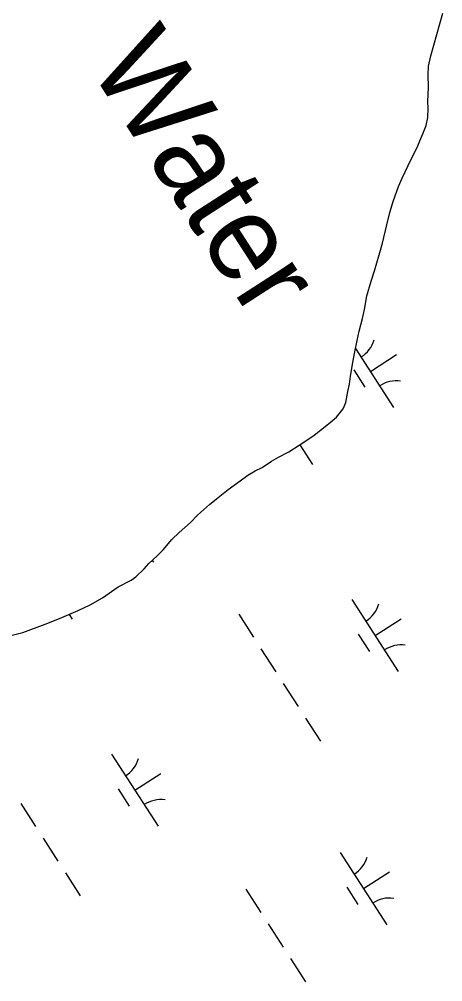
# Model space of a CAD drawing. Extents: x 3937982 to 3958556, y 219448 to 241894.
# Drawn here: x 3948264 to 3948510, y 226065 to 226625 of the extents above; entities that cross this region are included whole.
import ezdxf

# ---------------------------------------------------------------- set-up
doc = ezdxf.new("R2010")
doc.units = 0
for name, color, linetype in [('V-RIVR-IDEN', 7, 'Continuous'), ('V-TOPO-SHOR', 7, 'Continuous'), ('V-WETL-SWMP', 7, 'Continuous')]:
    doc.layers.add(name, color=color, linetype=linetype)

msp = doc.modelspace()

# ---------------------------------------------------------------- linework, layer by layer
at = {"layer": 'V-TOPO-SHOR'}
for points in [[(3948392.511, 226356.751), (3948396.945, 226360.011), (3948401.18, 226362.463), (3948405.217, 226364.507), (3948410.66, 226368.177), (3948414.898, 226370.426), (3948420.749, 226373.491), (3948426.797, 226377.366), (3948430.223, 226379.611), (3948435.667, 226383.281), (3948439.294, 226386.132), (3948444.936, 226390.613), (3948448.561, 226393.666), (3948452.378, 226398.543), (3948453.978, 226402.192), (3948455.157, 226408.674), (3948456.147, 226412.928), (3948456.728, 226417.583), (3948458.104, 226425.482), (3948459.088, 226430.745), (3948460.667, 226438.444), (3948461.852, 226443.709), (3948463.632, 226451.205), (3948464.82, 226456.47), (3948466.194, 226464.369), (3948468.779, 226472.879), (3948470.769, 226478.959), (3948473.352, 226488.28), (3948475.338, 226494.966), (3948477.913, 226505.702), (3948479.694, 226512.792), (3948481.482, 226519.276), (3948484.673, 226527.993), (3948486.873, 226532.861), (3948490.274, 226540.162), (3948492.474, 226544.624), (3948495.478, 226550.711), (3948497.076, 226554.561), (3948498.876, 226558.618), (3948500.873, 226563.484), (3948501.657, 226568.142), (3948502.034, 226573.606), (3948501.811, 226577.45), (3948501.991, 226581.497), (3948502.171, 226585.746), (3948501.932, 226593.029), (3948502.108, 226598.087), (3948503.492, 226603.961), (3948510.441, 226628.883)], [(3948257.437, 226266.211), (3948265.922, 226268.48), (3948279.05, 226273.203), (3948287.328, 226276.484), (3948298.227, 226281.194), (3948305.088, 226284.469), (3948312.35, 226288.553), (3948321.421, 226295.073), (3948329.087, 226298.959), (3948331.708, 226300.794), (3948336.539, 226305.471), (3948339.355, 226308.523), (3948344.187, 226312.998), (3948347.609, 226316.457), (3948352.635, 226322.552), (3948357.062, 226326.623), (3948363.505, 226332.523), (3948367.732, 226336.793), (3948374.579, 226342.898), (3948378.81, 226346.159), (3948385.458, 226351.658), (3948392.511, 226356.751)]]:
    msp.add_lwpolyline(points, dxfattribs=at)
at = {"layer": 'V-WETL-SWMP'}
for p, q in [((3948503.492, 226603.962), (3948510.441, 226628.883)), ((3948502.107, 226598.087), (3948503.492, 226603.962)), ((3948501.931, 226593.028), (3948502.107, 226598.087)), ((3948502.172, 226585.746), (3948501.931, 226593.028)), ((3948501.811, 226577.449), (3948501.992, 226581.496)), ((3948501.992, 226581.496), (3948502.172, 226585.746)), ((3948502.034, 226573.606), (3948501.811, 226577.449)), ((3948501.658, 226568.142), (3948502.034, 226573.606)), ((3948500.873, 226563.484), (3948501.658, 226568.142)), ((3948497.076, 226554.562), (3948498.876, 226558.618)), ((3948498.876, 226558.618), (3948500.873, 226563.484)), ((3948495.478, 226550.71), (3948497.076, 226554.562)), ((3948492.475, 226544.625), (3948495.478, 226550.71)), ((3948490.274, 226540.162), (3948492.475, 226544.625)), ((3948486.873, 226532.861), (3948490.274, 226540.162)), ((3948484.673, 226527.993), (3948486.873, 226532.861)), ((3948481.482, 226519.277), (3948484.673, 226527.993)), ((3948479.695, 226512.793), (3948481.482, 226519.277)), ((3948477.912, 226505.703), (3948479.695, 226512.793)), ((3948475.339, 226494.967), (3948477.912, 226505.703)), ((3948473.351, 226488.28), (3948475.339, 226494.967)), ((3948470.77, 226478.959), (3948473.351, 226488.28)), ((3948468.779, 226472.879), (3948470.77, 226478.959)), ((3948466.194, 226464.369), (3948468.779, 226472.879)), ((3948464.819, 226456.471), (3948466.194, 226464.369)), ((3948463.633, 226451.204), (3948464.819, 226456.471)), ((3948461.852, 226443.709), (3948463.633, 226451.204)), ((3948460.666, 226438.443), (3948461.852, 226443.709)), ((3948459.088, 226430.746), (3948460.666, 226438.443)), ((3948458.104, 226425.481), (3948459.088, 226430.746)), ((3948459.709, 226433.775), (3948481.857, 226399.367)), ((3948468.326, 226420.389), (3948483.461, 226430.131)), ((3948456.729, 226417.583), (3948458.104, 226425.481)), ((3948458.59, 226421.258), (3948465.085, 226411.168)), ((3948455.158, 226408.673), (3948456.147, 226412.927)), ((3948456.147, 226412.927), (3948456.729, 226417.583)), ((3948453.978, 226402.193), (3948455.158, 226408.673)), ((3948452.379, 226398.543), (3948453.978, 226402.193)), ((3948448.561, 226393.667), (3948452.379, 226398.543)), ((3948439.294, 226386.132), (3948444.935, 226390.613)), ((3948444.935, 226390.613), (3948448.561, 226393.667)), ((3948435.667, 226383.281), (3948439.294, 226386.132)), ((3948426.797, 226377.367), (3948430.224, 226379.61)), ((3948430.224, 226379.61), (3948435.667, 226383.281)), ((3948414.897, 226370.425), (3948420.748, 226373.491)), ((3948420.748, 226373.491), (3948426.797, 226377.367)), ((3948427.206, 226377.635), (3948434.568, 226366.198)), ((3948405.217, 226364.507), (3948410.66, 226368.177)), ((3948410.66, 226368.177), (3948414.897, 226370.425)), ((3948396.946, 226360.012), (3948401.181, 226362.462)), ((3948401.181, 226362.462), (3948405.217, 226364.507)), ((3948385.458, 226351.657), (3948392.512, 226356.752)), ((3948392.512, 226356.752), (3948396.946, 226360.012)), ((3948378.81, 226346.159), (3948385.458, 226351.657)), ((3948374.579, 226342.899), (3948378.81, 226346.159)), ((3948367.732, 226336.794), (3948374.579, 226342.899)), ((3948363.506, 226332.523), (3948367.732, 226336.794)), ((3948357.063, 226326.622), (3948363.506, 226332.523)), ((3948352.634, 226322.552), (3948357.063, 226326.622)), ((3948347.608, 226316.456), (3948352.634, 226322.552)), ((3948339.355, 226308.522), (3948344.187, 226312.998)), ((3948344.187, 226312.998), (3948347.608, 226316.456)), ((3948336.539, 226305.472), (3948339.355, 226308.522)), ((3948341.334, 226310.356), (3948341.99, 226309.338)), ((3948329.087, 226298.959), (3948331.708, 226300.794)), ((3948331.708, 226300.794), (3948336.539, 226305.472)), ((3948312.35, 226288.552), (3948321.42, 226295.074)), ((3948321.42, 226295.074), (3948329.087, 226298.959)), ((3948298.227, 226281.194), (3948305.088, 226284.468)), ((3948305.088, 226284.468), (3948312.35, 226288.552)), ((3948457.493, 226287.691), (3948484.555, 226245.648)), ((3948287.327, 226276.484), (3948298.227, 226281.194)), ((3948292.937, 226278.908), (3948294.701, 226276.169)), ((3948391.628, 226279.096), (3948400.288, 226265.642)), ((3948265.923, 226268.48), (3948279.049, 226273.203)), ((3948279.049, 226273.203), (3948287.327, 226276.484)), ((3948471.024, 226266.669), (3948486.16, 226276.412)), ((3948257.438, 226266.21), (3948265.923, 226268.48)), ((3948461.289, 226267.538), (3948467.784, 226257.448)), ((3948404.618, 226258.915), (3948413.278, 226245.461)), ((3948417.608, 226238.734), (3948426.268, 226225.281)), ((3948430.598, 226218.554), (3948439.258, 226205.1)), ((3948317.626, 226197.661), (3948344.688, 226155.618)), ((3948331.157, 226176.64), (3948346.293, 226186.382)), ((3948321.422, 226177.509), (3948327.917, 226167.419)), ((3948264.751, 226168.886), (3948273.411, 226155.432)), ((3948277.741, 226148.705), (3948286.401, 226135.251)), ((3948450.755, 226140.363), (3948477.817, 226098.319)), ((3948290.731, 226128.524), (3948299.39, 226115.07)), ((3948464.286, 226119.341), (3948479.422, 226129.084)), ((3948395.889, 226118.966), (3948404.549, 226105.512)), ((3948454.551, 226120.21), (3948461.046, 226110.12)), ((3948408.879, 226098.785), (3948417.539, 226085.331)), ((3948421.869, 226078.604), (3948430.529, 226065.15))]:
    msp.add_line(p, q, dxfattribs=at)
for centre, start, end in [((3948453.575, 226443.743), 301.99668, 343.54034), ((3948483.475, 226397.291), 81.99668, 123.54034), ((3948456.274, 226290.024), 301.99668, 343.54034), ((3948486.174, 226243.572), 81.99668, 123.54034), ((3948316.407, 226199.994), 301.99668, 343.54034), ((3948346.307, 226153.542), 81.99668, 123.54034), ((3948449.536, 226142.695), 301.99668, 343.54034), ((3948479.436, 226096.244), 81.99668, 123.54034)]:
    msp.add_arc(centre, 17.623, start, end, dxfattribs=at)

# ---------------------------------------------------------------- texts
at = {"layer": 'V-RIVR-IDEN'}
msp.add_text('Water', height=49.9999, rotation=302.76856, dxfattribs=at).set_placement((3948303.613, 226598.36))

doc.saveas('drawing.dxf')
